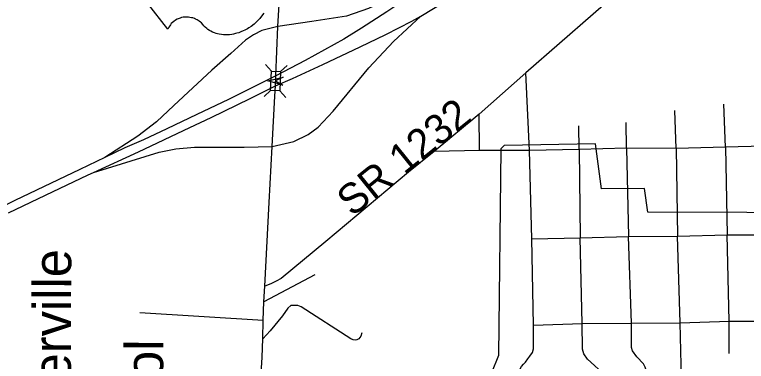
# Model space of a CAD drawing. Extents: x 2364794 to 2387902, y 795230 to 810426.
# Drawn here: x 2366377 to 2366996, y 800821 to 801114 of the extents above; entities that cross this region are included whole.
import ezdxf

# ---------------------------------------------------------------- set-up
doc = ezdxf.new("R2010")
doc.units = 0
for name, color, linetype in [('Default', 7, 'Continuous'), ('Plot Label CELL', 7, 'Continuous'), ('Plot Shape CELL', 7, 'Continuous')]:
    doc.layers.add(name, color=color, linetype=linetype)

msp = doc.modelspace()

# ---------------------------------------------------------------- linework, layer by layer
at = {"layer": 'Default'}
for p, q in [((2366506.47, 801102.1), (2366489.05, 801124.13)), ((2366515.26, 801110.98), (2366514.19, 801110.48)), ((2366516.71, 801111.52), (2366515.26, 801110.98)), ((2366517.99, 801111.86), (2366516.71, 801111.52)), ((2366519.44, 801112.14), (2366517.99, 801111.86)), ((2366520.96, 801112.3), (2366519.44, 801112.14)), ((2366522.26, 801112.34), (2366520.96, 801112.3)), ((2366523.83, 801112.27), (2366522.26, 801112.34)), ((2366525.09, 801112.09), (2366523.83, 801112.27)), ((2366526.43, 801111.83), (2366525.09, 801112.09)), ((2366527.46, 801111.57), (2366526.43, 801111.83)), ((2366528.94, 801111.06), (2366527.46, 801111.57)), ((2366529.9, 801110.66), (2366528.94, 801111.06)), ((2366584.13, 801111.06), (2366582.84, 801109.64)), ((2366585.71, 801112.99), (2366584.13, 801111.06)), ((2366587.5, 801115.56), (2366585.71, 801112.99)), ((2366507.96, 801104.97), (2366507.29, 801103.85)), ((2366508.6, 801105.85), (2366507.96, 801104.97)), ((2366509.33, 801106.78), (2366508.6, 801105.85)), ((2366510.31, 801107.75), (2366509.33, 801106.78)), ((2366511.41, 801108.72), (2366510.31, 801107.75)), ((2366512.75, 801109.65), (2366511.41, 801108.72)), ((2366514.19, 801110.48), (2366512.75, 801109.65)), ((2366531.18, 801109.98), (2366529.9, 801110.66)), ((2366532.05, 801109.47), (2366531.18, 801109.98)), ((2366533.02, 801108.83), (2366532.05, 801109.47)), ((2366534.07, 801108.03), (2366533.02, 801108.83)), ((2366534.82, 801107.37), (2366534.07, 801108.03)), ((2366536.06, 801106.09), (2366534.82, 801107.37)), ((2366536.93, 801105.02), (2366536.06, 801106.09)), ((2366538.04, 801103.85), (2366536.93, 801105.02)), ((2366579.31, 801106.34), (2366576.81, 801104.42)), ((2366580.71, 801107.56), (2366579.31, 801106.34)), ((2366582.84, 801109.64), (2366580.71, 801107.56)), ((2366506.75, 801102.78), (2366506.47, 801102.1)), ((2366507.29, 801103.85), (2366506.75, 801102.78)), ((2366539.26, 801102.72), (2366538.04, 801103.85)), ((2366540.36, 801101.86), (2366539.26, 801102.72)), ((2366541.65, 801100.99), (2366540.36, 801101.86)), ((2366542.86, 801100.29), (2366541.65, 801100.99)), ((2366544.31, 801099.56), (2366542.86, 801100.29)), ((2366545.83, 801098.93), (2366544.31, 801099.56)), ((2366547.2, 801098.46), (2366545.83, 801098.93)), ((2366564.78, 801098.59), (2366563.7, 801098.31)), ((2366566.47, 801099.13), (2366564.78, 801098.59)), ((2366568.25, 801099.78), (2366566.47, 801099.13)), ((2366570.2, 801100.61), (2366568.25, 801099.78)), ((2366571.54, 801101.24), (2366570.2, 801100.61)), ((2366573.68, 801102.4), (2366571.54, 801101.24)), ((2366575, 801103.2), (2366573.68, 801102.4)), ((2366576.81, 801104.42), (2366575, 801103.2)), ((2366548.33, 801098.14), (2366547.2, 801098.46)), ((2366549.9, 801097.78), (2366548.33, 801098.14)), ((2366551.73, 801097.49), (2366549.9, 801097.78)), ((2366553.46, 801097.31), (2366551.73, 801097.49)), ((2366554.94, 801097.26), (2366553.46, 801097.31)), ((2366556.72, 801097.28), (2366554.94, 801097.26)), ((2366558.65, 801097.41), (2366556.72, 801097.28)), ((2366560.48, 801097.65), (2366558.65, 801097.41)), ((2366561.82, 801097.9), (2366560.48, 801097.65)), ((2366563.7, 801098.31), (2366561.82, 801097.9)), ((2366594.15, 801066.66), (2366589.06, 801072.23)), ((2366601.69, 801066.32), (2366607.26, 801071.42)), ((2366587.82, 801045.06), (2366593.38, 801050.15)), ((2366606.19, 801044.24), (2366601.1, 801049.81))]:
    msp.add_line(p, q, dxfattribs=at)
for points in [[(2366603.68, 801054.66), (2366590.92, 801058.5), (2366603.89, 801061.56), (2366597.58, 801058.3)], [(2366593.38, 801050.15), (2366594.12, 801066.66), (2366601.83, 801066.32), (2366601.1, 801049.81)]]:
    msp.add_lwpolyline(points, close=True, dxfattribs=at)
msp.add_lwpolyline([(2366597.42, 801054.06), (2366597.79, 801062.52)], dxfattribs=at)
at = {"layer": 'Plot Label CELL'}
for p, q in [((2366812.33, 800999.6), (2366809.38, 801065.16)), ((2366978.25, 801002.33), (2366976.85, 801038.59)), ((2366936.51, 801001.31), (2366935.35, 801033.43)), ((2366770.14, 800999.47), (2366769.88, 801030.29)), ((2366854.53, 801000.19), (2366854.14, 801020.28)), ((2366894.52, 801001.4), (2366894.12, 801023.26)), ((2366770.14, 800999.47), (2366731.88, 800998.7)), ((2366812.33, 800999.6), (2366770.14, 800999.47)), ((2366854.53, 801000.19), (2366812.33, 800999.6)), ((2366814.29, 800924.86), (2366812.33, 800999.6)), ((2366894.52, 801001.4), (2366854.53, 801000.19)), ((2366854.53, 801000.19), (2366855.39, 800925.65)), ((2366894.52, 801001.4), (2366896.24, 800926.86)), ((2366936.51, 801001.31), (2366894.52, 801001.4)), ((2366978.25, 801002.33), (2366936.51, 801001.31)), ((2366936.51, 801001.31), (2366937.57, 800926.98)), ((2367019.34, 801003.34), (2366978.25, 801002.33)), ((2366978.25, 801002.33), (2366979.74, 800928.22)), ((2366814.29, 800924.86), (2366855.39, 800925.65)), ((2366855.39, 800925.65), (2366896.24, 800926.86)), ((2366857.09, 800853.07), (2366855.39, 800925.65)), ((2366896.24, 800926.86), (2366937.57, 800926.98)), ((2366898.62, 800853.42), (2366896.24, 800926.86)), ((2366937.57, 800926.98), (2366979.74, 800928.22)), ((2366939.92, 800853.75), (2366937.57, 800926.98)), ((2366981.47, 800855), (2366979.74, 800928.22)), ((2366979.74, 800928.22), (2367021.07, 800928.12)), ((2366815.77, 800851.62), (2366814.29, 800924.86)), ((2366630.68, 800894.43), (2366587.58, 800871.56)), ((2366482.74, 800862.58), (2366587.07, 800856.03)), ((2366815.77, 800851.62), (2366857.09, 800853.07)), ((2366857.09, 800853.07), (2366898.62, 800853.42)), ((2366898.62, 800853.42), (2366939.92, 800853.75)), ((2366939.92, 800853.75), (2366981.47, 800855)), ((2366942.02, 800762.61), (2366939.92, 800853.75)), ((2366981.47, 800855), (2367022.55, 800855.35)), ((2366981.47, 800827.9), (2366981.47, 800855))]:
    msp.add_line(p, q, dxfattribs=at)
for points in [[(2366923.32, 801164.77), (2366809.38, 801065.16), (2366769.88, 801030.29), (2366731.88, 800998.7), (2366709.97, 800981.02), (2366639.98, 800922.63), (2366602.18, 800891.19), (2366598.11, 800888.97), (2366593.63, 800886.75), (2366588.34, 800884.74)], [(2366788.16, 801000.92), (2366786.07, 800825.96), (2366768.32, 800782.08), (2366754.11, 800740.13), (2366744.07, 800730.01), (2366706.87, 800726.96), (2366678.73, 800721.27), (2366665.69, 800714.75), (2366645.89, 800697.21), (2366630.73, 800670.7), (2366626.28, 800655.17), (2366626.04, 800610.32), (2366611.08, 800601.61), (2366586.72, 800585.24), (2366554.22, 800557.13), (2366241.62, 800546.88), (2366175.9, 800494.71), (2366184.14, 800414.1)], [(2367162, 800774.1), (2367150.09, 800774.38), (2367149.29, 800872.8), (2367126.29, 800873.55), (2367123.38, 800903.52), (2367084.96, 800904.08), (2367080.14, 800946.86), (2366912.54, 800947.23), (2366909.63, 800967.26), (2366873.4, 800967.05), (2366868.38, 801005.24), (2366790.93, 801003.65), (2366788.16, 801000.92)], [(2366670.44, 800845.36), (2366669.59, 800842.31), (2366667.88, 800840.31), (2366666.34, 800839.2), (2366664.82, 800838.98), (2366663.29, 800839.4), (2366661.32, 800840.27), (2366619.11, 800867.22), (2366616.47, 800868.3), (2366612.33, 800868.48), (2366610.35, 800868.25), (2366607.96, 800866.04), (2366603.43, 800859.66), (2366593.05, 800846.89), (2366586.76, 800840.29)], [(2366802.53, 800810.98), (2366805.8, 800816.66), (2366807.23, 800818.88), (2366809.06, 800820.53), (2366811.11, 800823.34), (2366812.74, 800825.57), (2366814.99, 800828.6), (2366815.81, 800831.65), (2366815.77, 800851.62)], [(2366880.22, 800805.12), (2366874.76, 800810.83), (2366867.47, 800817.55), (2366861.6, 800823.06), (2366858.36, 800827.54), (2366857.36, 800831.4), (2366857.09, 800853.07)], [(2366901.78, 800781.39), (2366907.47, 800783.4), (2366909.71, 800785.02), (2366911.35, 800788.67), (2366911.98, 800792.93), (2366912.02, 800805.11), (2366911.64, 800811.81), (2366910.23, 800816.08), (2366908.82, 800818.93), (2366903.35, 800825.04), (2366899.72, 800830.13), (2366898.81, 800832.88), (2366898.62, 800853.42)]]:
    msp.add_lwpolyline(points, dxfattribs=at)
at = {"layer": 'Plot Shape CELL'}
for points in [[(2366599.61, 801104.46), (2366608.57, 801253.98)], [(2366720.42, 801113.24), (2366731.22, 801119.63), (2366755.27, 801134.44), (2366779.33, 801152.01), (2366797.05, 801166.97), (2366814.9, 801183.52), (2366827.07, 801194.06)], [(2366744.07, 801155.26), (2366730.49, 801144.67), (2366712.91, 801131.16), (2366691.76, 801116.87), (2366670.35, 801102.85), (2366655.42, 801093.55), (2366622.53, 801075.74), (2366597.79, 801062.52)], [(2366744.07, 801155.26), (2366716.86, 801141.43), (2366697.24, 801129.77), (2366676.25, 801119.56), (2366657.44, 801113.08), (2366628.37, 801108.52), (2366599.61, 801104.46)], [(2366594.58, 801002.94), (2366612.95, 801007.1), (2366625.27, 801013.05), (2366633.62, 801019.31), (2366646.26, 801032.87), (2366676.56, 801069.42), (2366697.37, 801091.68), (2366720.42, 801113.24)], [(2366597.42, 801054.06), (2366611.97, 801060.49), (2366637.45, 801072.26), (2366669.28, 801087.3), (2366690.93, 801097.64), (2366712.86, 801108.76), (2366720.42, 801113.24)], [(2366599.61, 801104.46), (2366585.88, 801100.95), (2366578.96, 801097.32), (2366572.04, 801092.88), (2366559.6, 801081.55), (2366543.71, 801067.39), (2366511.5, 801037.65), (2366496.84, 801023.74), (2366481.11, 801011.67), (2366453.1, 800993.55)], [(2366597.79, 801062.52), (2366599.61, 801104.46)], [(2366597.79, 801062.52), (2366557.62, 801042.5), (2366530.81, 801030.07), (2366505.45, 801017.77), (2366485.78, 801008.62), (2366470, 801001.69), (2366453.21, 800993.61), (2366453.1, 800993.55)], [(2366443.58, 800980.95), (2366481.66, 800998.49), (2366525.1, 801018.89), (2366543.19, 801027.52), (2366576.08, 801043.49), (2366597.42, 801054.06)], [(2366594.58, 801002.94), (2366596.95, 801045.56), (2366597.42, 801054.06)], [(2366443.58, 800980.95), (2366498.94, 800998.16), (2366513.17, 801000.96), (2366528.92, 801002.22), (2366571.08, 801002.38), (2366594.58, 801002.94)], [(2366588.34, 800884.74), (2366592.05, 800955.39), (2366594.58, 801002.94)], [(2366453.1, 800993.55), (2366431.97, 800983.38), (2366377.03, 800957.21), (2366357.09, 800947.66)], [(2366371.45, 800946.69), (2366402.88, 800961.6), (2366439.07, 800978.87), (2366443.58, 800980.95)], [(2366579.89, 800709.28), (2366580.53, 800725.23), (2366583.37, 800778.16), (2366586.25, 800824.76), (2366586.76, 800840.29), (2366587.07, 800856.03), (2366587.58, 800871.56), (2366588.34, 800884.74)]]:
    msp.add_lwpolyline(points, dxfattribs=at)

# ---------------------------------------------------------------- texts
at = {"layer": 'Default'}
for s, height, p in [('Baskerville', 32.0361, (2366423.97, 800708.88)), ('School', 32.036, (2366502.06, 800708.6))]:
    msp.add_text(s, height=height, rotation=89.79762, dxfattribs=at).set_placement(p)
at = {"layer": 'Plot Label CELL'}
msp.add_text('SR 1232', height=25.362, rotation=38.902, dxfattribs=at).set_placement((2366662.55, 800942.75))

doc.saveas('drawing.dxf')
